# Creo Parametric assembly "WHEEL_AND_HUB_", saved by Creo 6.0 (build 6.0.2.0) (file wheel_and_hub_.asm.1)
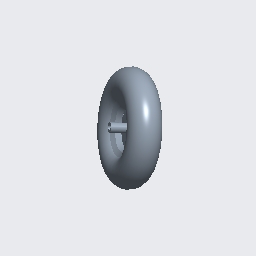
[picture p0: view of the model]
Units: Inch lbm Second (Pro/E Default); INCH, POUND, SECS

Created from: INLBS_ASM_DESIGN.ASM

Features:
  1. datum plane "ASM_RIGHT"
  2. datum plane "ASM_TOP"
  3. datum plane "ASM_FRONT"
  4. coordinate system
  5. component "HUB_", "HUB.PRT"
  6. component "WHEEL_", "WHEEL.PRT"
